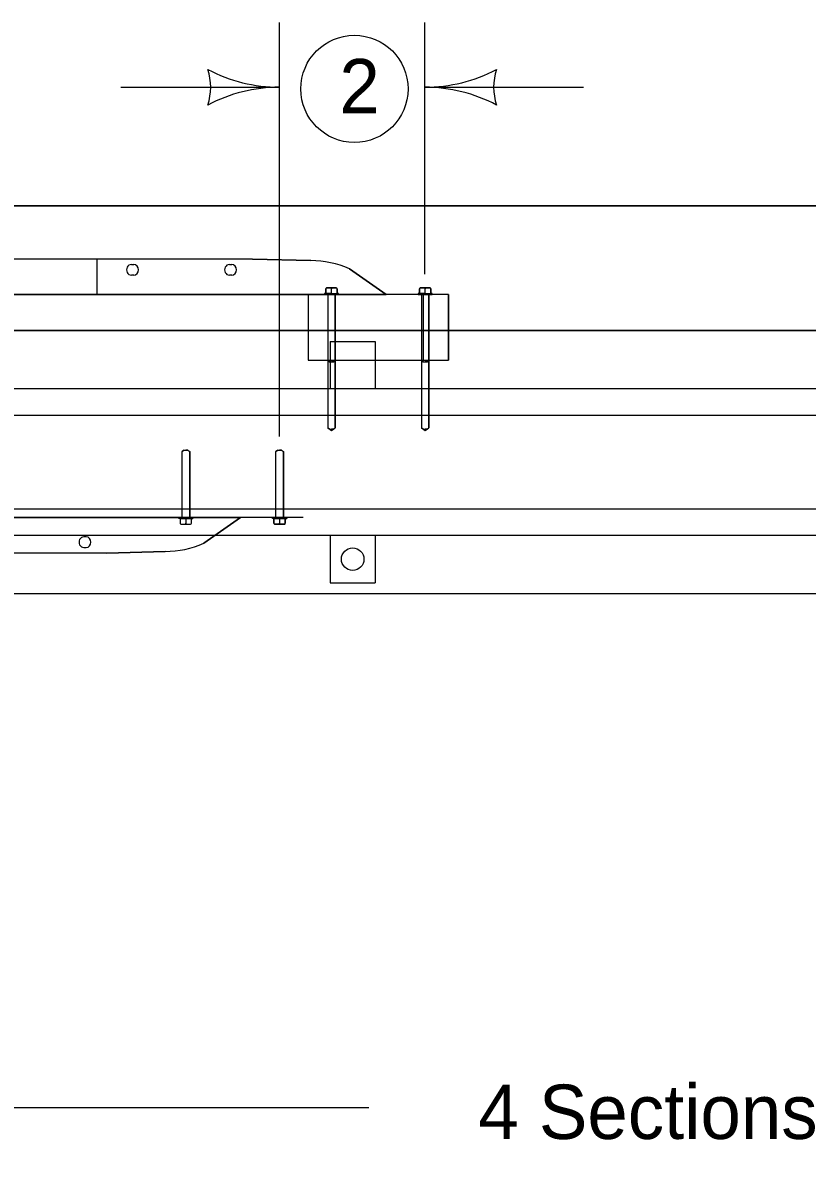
# Model space of a CAD drawing. Extents: x -2137026 to -2131464, y -2138478 to -2136524.
# Drawn here: x -2136526.6 to -2136307.1, y -2137863.1 to -2137546.2 of the extents above; entities that cross this region are included whole.
import ezdxf

# ---------------------------------------------------------------- set-up
doc = ezdxf.new("R2010")
doc.units = 0
for name, color, linetype in [('conPaving', 7, 'Continuous'), ('Level 2', 7, 'Continuous'), ('Level 3', 7, 'Continuous'), ('Level 41', 7, 'Continuous'), ('Level 9', 7, 'Continuous')]:
    doc.layers.add(name, color=color, linetype=linetype)

msp = doc.modelspace()

# ---------------------------------------------------------------- linework, layer by layer
at = {"layer": 'conPaving'}
for p, q in [((-2136462.32, -2137612.31), (-2136747.4, -2137612.31)), ((-2136446, -2137612.74), (-2136462.32, -2137612.31)), ((-2136496.17, -2137613.85), (-2136495.5, -2137613.85)), ((-2136495.5, -2137616.82), (-2136496.17, -2137616.82)), ((-2136468.75, -2137613.85), (-2136468.08, -2137613.85)), ((-2136468.08, -2137616.82), (-2136468.75, -2137616.82)), ((-2136424.91, -2137622.22), (-2136435.17, -2137615.07)), ((-2136768.45, -2137622.22), (-2136441.26, -2137622.22)), ((-2136441.79, -2137621.92), (-2136442.19, -2137621.92)), ((-2136442.19, -2137621.92), (-2136442.19, -2137622.22)), ((-2136442.19, -2137622.22), (-2136441.26, -2137622.22)), ((-2136441.79, -2137620.66), (-2136441.79, -2137621.92)), ((-2136439.91, -2137620.35), (-2136441.51, -2137620.35)), ((-2136441.26, -2137622.22), (-2136441.26, -2137640.7)), ((-2136441.26, -2137622.22), (-2136441.26, -2137659.5)), ((-2136438.89, -2137620.35), (-2136439.91, -2137620.35)), ((-2136439.14, -2137640.7), (-2136439.14, -2137622.22)), ((-2136439.14, -2137622.22), (-2136424.91, -2137622.22)), ((-2136439.14, -2137659.5), (-2136439.14, -2137622.22)), ((-2136439.14, -2137622.22), (-2136438.21, -2137622.22)), ((-2136438.6, -2137621.92), (-2136438.6, -2137620.66)), ((-2136438.21, -2137621.92), (-2136438.6, -2137621.92)), ((-2136438.21, -2137622.22), (-2136438.21, -2137621.92)), ((-2136415.58, -2137621.92), (-2136415.97, -2137621.92)), ((-2136415.97, -2137621.92), (-2136415.97, -2137622.22)), ((-2136415.58, -2137621.92), (-2136415.97, -2137621.92)), ((-2136415.97, -2137621.92), (-2136415.97, -2137622.22)), ((-2136415.97, -2137622.22), (-2136415.04, -2137622.22)), ((-2136415.97, -2137622.22), (-2136415.04, -2137622.22)), ((-2136415.58, -2137620.66), (-2136415.58, -2137621.92)), ((-2136415.58, -2137620.66), (-2136415.58, -2137621.92)), ((-2136413.7, -2137620.35), (-2136415.29, -2137620.35)), ((-2136413.7, -2137620.35), (-2136415.29, -2137620.35)), ((-2136415.04, -2137622.22), (-2136415.04, -2137640.7)), ((-2136415.04, -2137622.22), (-2136415.04, -2137659.5)), ((-2136412.67, -2137620.35), (-2136413.7, -2137620.35)), ((-2136412.67, -2137620.35), (-2136413.7, -2137620.35)), ((-2136412.92, -2137640.7), (-2136412.92, -2137622.22)), ((-2136412.92, -2137622.22), (-2136411.99, -2137622.22)), ((-2136412.92, -2137659.5), (-2136412.92, -2137622.22)), ((-2136412.92, -2137622.22), (-2136411.99, -2137622.22)), ((-2136412.39, -2137621.92), (-2136412.39, -2137620.66)), ((-2136412.39, -2137621.92), (-2136412.39, -2137620.66)), ((-2136411.99, -2137621.92), (-2136412.39, -2137621.92)), ((-2136411.99, -2137621.92), (-2136412.39, -2137621.92)), ((-2136411.99, -2137622.22), (-2136411.99, -2137621.92)), ((-2136411.99, -2137622.22), (-2136411.99, -2137621.92)), ((-2136441.26, -2137640.7), (-2136440.73, -2137641.09)), ((-2136440.73, -2137641.09), (-2136440.2, -2137641.09)), ((-2136440.2, -2137641.09), (-2136439.67, -2137641.09)), ((-2136439.67, -2137641.09), (-2136439.14, -2137640.7)), ((-2136415.04, -2137640.7), (-2136414.51, -2137641.09)), ((-2136414.51, -2137641.09), (-2136413.98, -2137641.09)), ((-2136413.98, -2137641.09), (-2136413.45, -2137641.09)), ((-2136413.45, -2137641.09), (-2136412.92, -2137640.7)), ((-2136441.26, -2137659.5), (-2136440.19, -2137660.28)), ((-2136440.19, -2137660.27), (-2136439.14, -2137659.5)), ((-2136440.19, -2137660.28), (-2136440.19, -2137660.25)), ((-2136440.19, -2137660.25), (-2136440.19, -2137660.27)), ((-2136415.04, -2137659.5), (-2136413.98, -2137660.28)), ((-2136413.98, -2137660.27), (-2136412.92, -2137659.5)), ((-2136413.98, -2137660.28), (-2136413.98, -2137660.25)), ((-2136413.98, -2137660.25), (-2136413.98, -2137660.27)), ((-2136481.98, -2137666.16), (-2136481.45, -2137665.78)), ((-2136481.98, -2137684.65), (-2136481.98, -2137666.16)), ((-2136481.45, -2137665.78), (-2136480.92, -2137665.78)), ((-2136480.92, -2137665.78), (-2136480.39, -2137665.78)), ((-2136480.39, -2137665.78), (-2136479.86, -2137666.16)), ((-2136479.86, -2137666.16), (-2136479.86, -2137684.65)), ((-2136455.76, -2137666.16), (-2136455.23, -2137665.78)), ((-2136455.76, -2137684.65), (-2136455.76, -2137666.16)), ((-2136455.23, -2137665.78), (-2136454.7, -2137665.78)), ((-2136454.7, -2137665.78), (-2136454.17, -2137665.78)), ((-2136454.17, -2137665.78), (-2136453.64, -2137666.16)), ((-2136453.64, -2137666.16), (-2136453.64, -2137684.65)), ((-2136809.17, -2137684.65), (-2136481.98, -2137684.65)), ((-2136479.86, -2137684.65), (-2136465.63, -2137684.65)), ((-2136465.63, -2137684.65), (-2136475.89, -2137691.8)), ((-2136456.69, -2137684.95), (-2136456.69, -2137684.65)), ((-2136456.69, -2137684.65), (-2136455.76, -2137684.65)), ((-2136456.3, -2137684.95), (-2136456.69, -2137684.95)), ((-2136456.3, -2137686.21), (-2136456.3, -2137684.95)), ((-2136454.42, -2137686.52), (-2136456.01, -2137686.52)), ((-2136453.39, -2137686.52), (-2136454.42, -2137686.52)), ((-2136453.64, -2137684.65), (-2136452.71, -2137684.65)), ((-2136452.71, -2137684.95), (-2136453.11, -2137684.95)), ((-2136453.11, -2137684.95), (-2136453.11, -2137686.21)), ((-2136452.71, -2137684.65), (-2136452.71, -2137684.95)), ((-2136508.8, -2137690.05), (-2136509.47, -2137690.05)), ((-2136509.47, -2137693.02), (-2136508.8, -2137693.02)), ((-2136503.04, -2137694.56), (-2136788.12, -2137694.56)), ((-2136486.72, -2137694.13), (-2136503.04, -2137694.56))]:
    msp.add_line(p, q, dxfattribs=at)
for centre, major_axis, ratio, start_param, end_param in [((-2136446, -2137638.28), (25.97, 0), 0.98332, 1.140354, 1.570796), ((-2136496.17, -2137615.33), (0, 1.49), 0.899999, 0, 3.141593), ((-2136495.5, -2137615.33), (0, 1.49), 0.899999, 3.141593, 6.283185), ((-2136468.75, -2137615.33), (0, 1.49), 0.899999, 0, 3.141593), ((-2136468.08, -2137615.33), (0, 1.49), 0.899999, 3.141593, 6.283185), ((-2136441.51, -2137620.66), (0, 0.315), 0.899999, 0, 1.570796), ((-2136438.89, -2137620.66), (0, 0.315), 0.899999, 4.712389, 6.283185), ((-2136415.29, -2137620.66), (0, -0.315), 0.899999, 3.141593, 4.712389), ((-2136415.29, -2137620.66), (0, 0.315), 0.899999, 0, 1.570796), ((-2136412.67, -2137620.66), (0, -0.315), 0.899999, 1.570796, 3.141593), ((-2136412.67, -2137620.66), (0, 0.315), 0.899999, 4.712389, 6.283185), ((-2136456.01, -2137686.21), (0, -0.315), 0.899999, 4.712389, 6.283185), ((-2136453.39, -2137686.21), (0, -0.315), 0.899999, 6.283185, 7.853982), ((-2136509.47, -2137691.53), (0, 1.49), 0.899999, 0, 3.141593), ((-2136508.8, -2137691.53), (0, 1.49), 0.899999, 3.141593, 6.283185), ((-2136486.72, -2137668.59), (25.97, 0), 0.98332, 4.712389, 5.142831)]:
    msp.add_ellipse(centre, major_axis=major_axis, ratio=ratio, start_param=start_param, end_param=end_param, dxfattribs=at)
at = {"layer": 'Level 2'}
for p, q in [((-2136454.76, -2137662), (-2136454.76, -2137546.17)), ((-2136414.04, -2137616.51), (-2136414.04, -2137546.17)), ((-2136499.14, -2137564.24), (-2136454.76, -2137564.24)), ((-2136414.04, -2137564.24), (-2136369.66, -2137564.24)), ((-2136188.5, -2137632.29), (-2136680.02, -2137632.29)), ((-2136188.5, -2137648.67), (-2136680.02, -2137648.67)), ((-2136188.5, -2137656.04), (-2136680.02, -2137656.04)), ((-2136188.5, -2137682.26), (-2136680.02, -2137682.26)), ((-2136188.5, -2137689.63), (-2136680.02, -2137689.63)), ((-2136188.5, -2137706.01), (-2136680.02, -2137706.01)), ((-2136681.05, -2137849.7), (-2136429.72, -2137849.7))]:
    msp.add_line(p, q, dxfattribs=at)
msp.add_circle((-2136433.77, -2137564.7), 15, dxfattribs=at)
for centre, radius, start, end in [((-2136490.4, -2137564.24), 16.42, 342.2666, 17.7333), ((-2136454.76, -2137521.74), 42.5, 241.9275, 270), ((-2136490.4, -2137564.24), 16.42, 342.2666, 17.7333), ((-2136454.76, -2137521.74), 42.5, 241.9275, 270), ((-2136414.04, -2137521.74), 42.5, 270, 298.0725), ((-2136378.41, -2137564.24), 16.42, 162.2666, 197.7334), ((-2136454.76, -2137606.74), 42.5, 90, 118.0725), ((-2136454.76, -2137606.74), 42.5, 90, 118.0725), ((-2136414.04, -2137606.74), 42.5, 61.9275, 90)]:
    msp.add_arc(centre, radius, start, end, dxfattribs=at)
at = {"layer": 'Level 41'}
for p, q in [((-2136440.55, -2137635.41), (-2136427.97, -2137635.41)), ((-2136440.55, -2137635.41), (-2136440.55, -2137648.67)), ((-2136427.97, -2137635.41), (-2136427.97, -2137648.67)), ((-2136440.55, -2137689.63), (-2136440.55, -2137702.89)), ((-2136427.97, -2137689.63), (-2136427.97, -2137702.89)), ((-2136440.55, -2137702.89), (-2136427.97, -2137702.89))]:
    msp.add_line(p, q, dxfattribs=at)
msp.add_circle((-2136434.26, -2137696.26), 3.15, dxfattribs=at)
at = {"layer": 'Level 9'}
for p, q in [((-2136691.9, -2137597.41), (-2134672.37, -2137597.41)), ((-2136191.5, -2137597.41), (-2136601.44, -2137597.41)), ((-2136462.32, -2137612.31), (-2136747.4, -2137612.31)), ((-2136505.73, -2137622.22), (-2136505.73, -2137612.31)), ((-2136407.43, -2137622.22), (-2136802.28, -2137622.22)), ((-2136446.75, -2137622.22), (-2136446.75, -2137640.62)), ((-2136407.43, -2137622.22), (-2136446.75, -2137622.22)), ((-2136446.75, -2137622.22), (-2136446.75, -2137640.62)), ((-2136440.2, -2137621.92), (-2136442.19, -2137621.92)), ((-2136442.19, -2137621.92), (-2136442.19, -2137622.22)), ((-2136440.2, -2137621.92), (-2136442.19, -2137621.92)), ((-2136442.19, -2137621.92), (-2136442.19, -2137622.22)), ((-2136442.19, -2137622.22), (-2136438.21, -2137622.22)), ((-2136442.19, -2137622.22), (-2136438.21, -2137622.22)), ((-2136441.79, -2137621.92), (-2136441.79, -2137620.66)), ((-2136441.79, -2137621.92), (-2136441.79, -2137620.66)), ((-2136441.79, -2137621.92), (-2136438.6, -2137621.92)), ((-2136441.79, -2137621.92), (-2136438.6, -2137621.92)), ((-2136441.51, -2137620.35), (-2136440.48, -2137620.35)), ((-2136441.51, -2137620.35), (-2136440.48, -2137620.35)), ((-2136441.26, -2137622.22), (-2136441.26, -2137640.7)), ((-2136441.26, -2137622.22), (-2136441.26, -2137659.5)), ((-2136440.48, -2137620.35), (-2136438.89, -2137620.35)), ((-2136440.48, -2137620.35), (-2136438.89, -2137620.35)), ((-2136440.2, -2137621.92), (-2136440.2, -2137620.66)), ((-2136440.2, -2137621.92), (-2136440.2, -2137620.66)), ((-2136440.2, -2137621.92), (-2136438.21, -2137621.92)), ((-2136440.2, -2137621.92), (-2136438.21, -2137621.92)), ((-2136440.2, -2137622.22), (-2136439.14, -2137622.22)), ((-2136440.2, -2137622.22), (-2136439.14, -2137622.22)), ((-2136439.14, -2137622.22), (-2136439.14, -2137640.7)), ((-2136439.14, -2137622.22), (-2136439.14, -2137659.5)), ((-2136438.6, -2137620.66), (-2136438.6, -2137621.92)), ((-2136438.6, -2137620.66), (-2136438.6, -2137621.92)), ((-2136438.21, -2137622.22), (-2136438.21, -2137621.92)), ((-2136438.21, -2137622.22), (-2136438.21, -2137621.92)), ((-2136413.98, -2137621.92), (-2136415.97, -2137621.92)), ((-2136415.97, -2137621.92), (-2136415.97, -2137622.22)), ((-2136413.98, -2137621.92), (-2136415.97, -2137621.92)), ((-2136415.97, -2137621.92), (-2136415.97, -2137622.22)), ((-2136415.97, -2137622.22), (-2136411.99, -2137622.22)), ((-2136415.97, -2137622.22), (-2136411.99, -2137622.22)), ((-2136415.58, -2137621.92), (-2136415.58, -2137620.66)), ((-2136415.58, -2137621.92), (-2136415.58, -2137620.66)), ((-2136415.58, -2137621.92), (-2136412.39, -2137621.92)), ((-2136415.58, -2137621.92), (-2136412.39, -2137621.92)), ((-2136415.29, -2137620.35), (-2136414.27, -2137620.35)), ((-2136415.29, -2137620.35), (-2136414.27, -2137620.35)), ((-2136415.04, -2137622.22), (-2136415.04, -2137640.7)), ((-2136415.04, -2137622.22), (-2136415.04, -2137659.5)), ((-2136414.56, -2137622.22), (-2136414.56, -2137640.62)), ((-2136414.27, -2137620.35), (-2136412.67, -2137620.35)), ((-2136414.27, -2137620.35), (-2136412.67, -2137620.35)), ((-2136413.98, -2137621.92), (-2136413.98, -2137620.66)), ((-2136413.98, -2137621.92), (-2136413.98, -2137620.66)), ((-2136413.98, -2137621.92), (-2136411.99, -2137621.92)), ((-2136413.98, -2137621.92), (-2136411.99, -2137621.92)), ((-2136413.98, -2137622.22), (-2136412.92, -2137622.22)), ((-2136413.98, -2137622.22), (-2136412.92, -2137622.22)), ((-2136412.92, -2137622.22), (-2136412.92, -2137640.7)), ((-2136412.92, -2137622.22), (-2136412.92, -2137659.5)), ((-2136412.39, -2137620.66), (-2136412.39, -2137621.92)), ((-2136412.39, -2137620.66), (-2136412.39, -2137621.92)), ((-2136411.99, -2137622.22), (-2136411.99, -2137621.92)), ((-2136411.99, -2137622.22), (-2136411.99, -2137621.92)), ((-2136407.43, -2137640.62), (-2136407.43, -2137622.22)), ((-2136407.43, -2137622.22), (-2136407.43, -2137640.62)), ((-2136601.44, -2137632.29), (-2136188.5, -2137632.29)), ((-2136446.75, -2137640.62), (-2136407.43, -2137640.62)), ((-2136446.75, -2137640.62), (-2136407.43, -2137640.62)), ((-2136440.73, -2137641.09), (-2136441.26, -2137640.7)), ((-2136440.73, -2137641.09), (-2136440.2, -2137641.09)), ((-2136439.67, -2137641.09), (-2136440.2, -2137641.09)), ((-2136439.67, -2137641.09), (-2136439.14, -2137640.7)), ((-2136414.51, -2137641.09), (-2136415.04, -2137640.7)), ((-2136414.51, -2137641.09), (-2136413.98, -2137641.09)), ((-2136413.45, -2137641.09), (-2136413.98, -2137641.09)), ((-2136413.45, -2137641.09), (-2136412.92, -2137640.7)), ((-2136440.73, -2137659.89), (-2136441.26, -2137659.5)), ((-2136440.73, -2137659.89), (-2136440.2, -2137659.89)), ((-2136439.67, -2137659.89), (-2136440.2, -2137659.89)), ((-2136439.67, -2137659.89), (-2136439.14, -2137659.5)), ((-2136414.51, -2137659.89), (-2136415.04, -2137659.5)), ((-2136414.51, -2137659.89), (-2136413.98, -2137659.89)), ((-2136413.45, -2137659.89), (-2136413.98, -2137659.89)), ((-2136413.45, -2137659.89), (-2136412.92, -2137659.5)), ((-2136481.45, -2137665.78), (-2136481.98, -2137666.16)), ((-2136481.98, -2137684.65), (-2136481.98, -2137666.16)), ((-2136481.45, -2137665.78), (-2136480.92, -2137665.78)), ((-2136480.39, -2137665.78), (-2136480.92, -2137665.78)), ((-2136480.39, -2137665.78), (-2136479.86, -2137666.16)), ((-2136479.86, -2137684.65), (-2136479.86, -2137666.16)), ((-2136455.23, -2137665.78), (-2136455.76, -2137666.16)), ((-2136455.76, -2137684.65), (-2136455.76, -2137666.16)), ((-2136455.23, -2137665.78), (-2136454.7, -2137665.78)), ((-2136454.17, -2137665.78), (-2136454.7, -2137665.78)), ((-2136454.17, -2137665.78), (-2136453.64, -2137666.16)), ((-2136453.64, -2137684.65), (-2136453.64, -2137666.16)), ((-2136448.15, -2137684.65), (-2136843, -2137684.65)), ((-2136482.91, -2137684.95), (-2136482.91, -2137684.65)), ((-2136482.91, -2137684.65), (-2136478.93, -2137684.65)), ((-2136480.92, -2137684.95), (-2136482.91, -2137684.95)), ((-2136482.51, -2137684.95), (-2136479.32, -2137684.95)), ((-2136482.51, -2137684.95), (-2136482.51, -2137686.21)), ((-2136482.23, -2137686.52), (-2136481.2, -2137686.52)), ((-2136481.2, -2137686.52), (-2136479.61, -2137686.52)), ((-2136480.92, -2137684.65), (-2136479.86, -2137684.65)), ((-2136480.92, -2137684.95), (-2136478.93, -2137684.95)), ((-2136480.92, -2137684.95), (-2136480.92, -2137686.21)), ((-2136479.32, -2137686.21), (-2136479.32, -2137684.95)), ((-2136478.93, -2137684.65), (-2136478.93, -2137684.95)), ((-2136456.69, -2137684.95), (-2136456.69, -2137684.65)), ((-2136456.69, -2137684.65), (-2136452.71, -2137684.65)), ((-2136454.7, -2137684.95), (-2136456.69, -2137684.95)), ((-2136456.3, -2137684.95), (-2136453.11, -2137684.95)), ((-2136456.3, -2137684.95), (-2136456.3, -2137686.21)), ((-2136456.01, -2137686.52), (-2136454.99, -2137686.52)), ((-2136454.99, -2137686.52), (-2136453.39, -2137686.52)), ((-2136454.7, -2137684.65), (-2136453.64, -2137684.65)), ((-2136454.7, -2137684.95), (-2136452.71, -2137684.95)), ((-2136454.7, -2137684.95), (-2136454.7, -2137686.21)), ((-2136453.11, -2137686.21), (-2136453.11, -2137684.95)), ((-2136452.71, -2137684.65), (-2136452.71, -2137684.95)), ((-2136503.04, -2137694.56), (-2136788.12, -2137694.56))]:
    msp.add_line(p, q, dxfattribs=at)
for points in [[(-2136462.32, -2137612.31), (-2136446, -2137612.74)], [(-2136496.17, -2137613.85), (-2136495.5, -2137613.85)], [(-2136495.5, -2137616.82), (-2136496.17, -2137616.82)], [(-2136468.75, -2137613.85), (-2136468.08, -2137613.85)], [(-2136468.08, -2137616.82), (-2136468.75, -2137616.82)], [(-2136435.17, -2137615.07), (-2136424.91, -2137622.22)], [(-2136475.89, -2137691.8), (-2136465.63, -2137684.65)], [(-2136508.8, -2137690.05), (-2136509.47, -2137690.05)], [(-2136509.47, -2137693.02), (-2136508.8, -2137693.02)], [(-2136503.04, -2137694.56), (-2136486.72, -2137694.13)]]:
    msp.add_lwpolyline(points, dxfattribs=at)
for centre, major_axis, ratio, start_param, end_param in [((-2136446, -2137638.28), (25.97, 0), 0.98332, 1.140354, 1.570796), ((-2136496.17, -2137615.33), (0, 1.49), 0.899999, 0, 3.141593), ((-2136495.5, -2137615.33), (0, 1.49), 0.899999, 3.141593, 6.283185), ((-2136468.75, -2137615.33), (0, 1.49), 0.899999, 0, 3.141593), ((-2136468.08, -2137615.33), (0, 1.49), 0.899999, 3.141593, 6.283185), ((-2136441.51, -2137620.66), (0, 0.315), 0.899999, 6.283185, 7.853982), ((-2136441.51, -2137620.66), (0, 0.315), 0.899999, 6.283185, 7.853982), ((-2136440.48, -2137620.66), (0, 0.315), 0.899999, 4.712389, 6.283185), ((-2136440.48, -2137620.66), (0, 0.315), 0.899999, 4.712389, 6.283185), ((-2136439.91, -2137620.66), (0, 0.315), 0.899999, 0, 1.570796), ((-2136439.91, -2137620.66), (0, 0.315), 0.899999, 0, 1.570796), ((-2136438.89, -2137620.66), (0, 0.315), 0.899999, 4.712389, 6.283185), ((-2136438.89, -2137620.66), (0, 0.315), 0.899999, 4.712389, 6.283185), ((-2136415.29, -2137620.66), (0, 0.315), 0.899999, 6.283185, 7.853982), ((-2136415.29, -2137620.66), (0, 0.315), 0.899999, 6.283185, 7.853982), ((-2136414.27, -2137620.66), (0, 0.315), 0.899999, 4.712389, 6.283185), ((-2136414.27, -2137620.66), (0, 0.315), 0.899999, 4.712389, 6.283185), ((-2136413.7, -2137620.66), (0, 0.315), 0.899999, 0, 1.570796), ((-2136413.7, -2137620.66), (0, 0.315), 0.899999, 0, 1.570796), ((-2136412.67, -2137620.66), (0, 0.315), 0.899999, 4.712389, 6.283185), ((-2136412.67, -2137620.66), (0, 0.315), 0.899999, 4.712389, 6.283185), ((-2136482.23, -2137686.21), (0, 0.315), 0.899999, 1.570796, 3.141593), ((-2136481.2, -2137686.21), (0, 0.315), 0.899999, 3.141593, 4.712389), ((-2136480.63, -2137686.21), (0, 0.315), 0.899999, 1.570796, 3.141593), ((-2136479.61, -2137686.21), (0, 0.315), 0.899999, 3.141593, 4.712389), ((-2136456.01, -2137686.21), (0, 0.315), 0.899999, 1.570796, 3.141593), ((-2136454.99, -2137686.21), (0, 0.315), 0.899999, 3.141593, 4.712389), ((-2136454.42, -2137686.21), (0, 0.315), 0.899999, 1.570796, 3.141593), ((-2136453.39, -2137686.21), (0, 0.315), 0.899999, 3.141593, 4.712389), ((-2136509.47, -2137691.53), (0, 1.49), 0.899999, 0, 3.141593), ((-2136508.8, -2137691.53), (0, 1.49), 0.899999, 3.141593, 6.283185), ((-2136486.72, -2137668.59), (25.97, 0), 0.98332, 4.712389, 5.142831)]:
    msp.add_ellipse(centre, major_axis=major_axis, ratio=ratio, start_param=start_param, end_param=end_param, dxfattribs=at)

# ---------------------------------------------------------------- texts
at = {"layer": 'Level 2'}
msp.add_text('2', height=15.2, dxfattribs=at).set_placement((-2136437.98, -2137571.54))
at = {"layer": 'Level 3'}
msp.add_text('4 Sections Anchored Temporary Barrier Rail, Concrete', height=15.2, dxfattribs=at).set_placement((-2136399.13, -2137858.5))

doc.saveas('drawing.dxf')
